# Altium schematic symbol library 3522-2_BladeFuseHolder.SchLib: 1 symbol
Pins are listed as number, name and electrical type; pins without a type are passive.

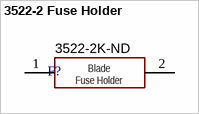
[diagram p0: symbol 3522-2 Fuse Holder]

## 3522-2 Fuse Holder
designator F?  Supplier Part Number: 3522-2K-ND  (hidden comment: *)
Description FUSE CLIP BLADE 500V 30A PCB; Part Number: 3522-2; Manufacturer: Keystone Electronics; Name: Blade Fuse Holder; Number of Positions: 2; Color: Black; Connector Usage: Receptacle; Note: Fuse Not Provided
footprint 3522-2_BladeFuseHolder
pins: 1, 2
